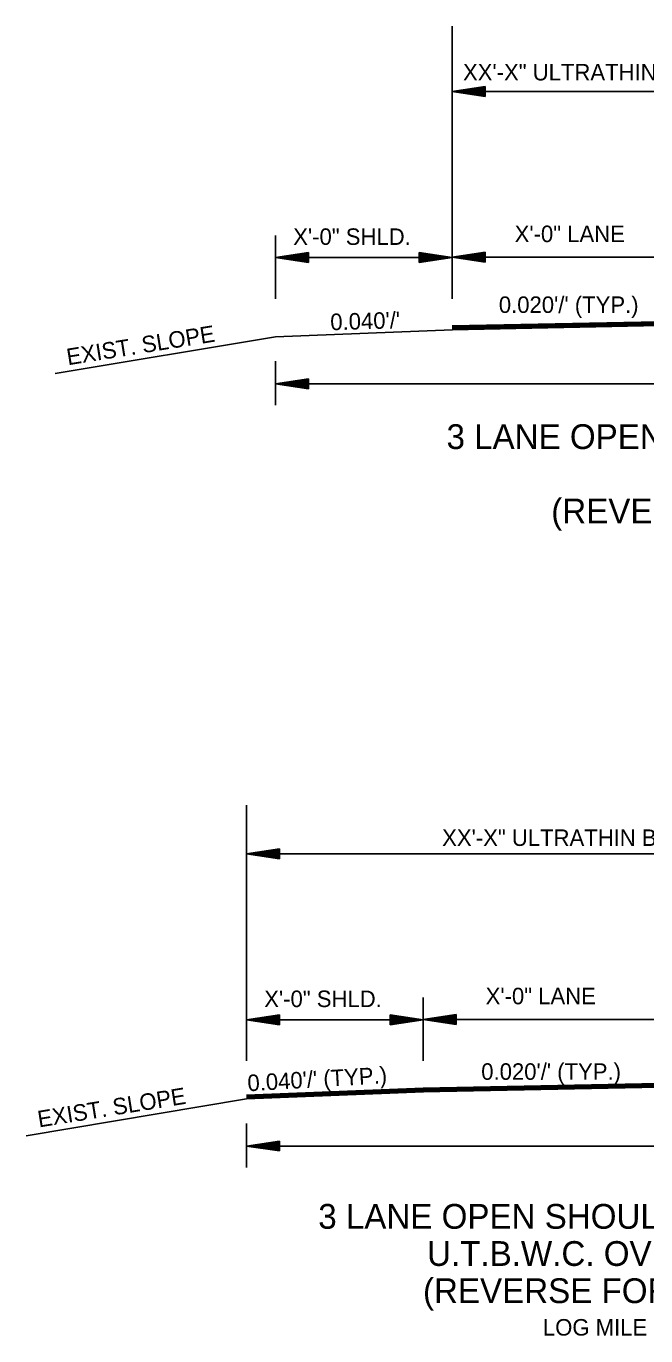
# Model space of a CAD drawing. Extents: x 544199 to 1930787, y -1968972 to 596640.
# Drawn here: x 551580 to 551862, y -1953290 to -1952695 of the extents above; entities that cross this region are included whole.
import ezdxf

# ---------------------------------------------------------------- set-up
doc = ezdxf.new("R2010")
doc.units = 0
doc.layers.add('R_Draft', color=7, linetype='Continuous')

msp = doc.modelspace()

# ---------------------------------------------------------------- linework, layer by layer
at = {"layer": 'R_Draft'}
for p, q in [((551773.61, -1952818.73), (551773.61, -1952695)), ((551788.61, -1952722.45), (551773.61, -1952724.7)), ((551773.61, -1952724.7), (552133.8, -1952724.7)), ((551788.61, -1952726.95), (551773.61, -1952724.7)), ((551788.61, -1952722.83), (551776.12, -1952724.7)), ((551788.61, -1952726.58), (551776.12, -1952724.7)), ((551788.61, -1952723.21), (551778.7, -1952724.7)), ((551788.61, -1952726.19), (551778.7, -1952724.7)), ((551788.61, -1952723.58), (551781.19, -1952724.7)), ((551788.61, -1952725.82), (551781.19, -1952724.7)), ((551788.61, -1952723.97), (551783.74, -1952724.7)), ((551788.61, -1952725.43), (551783.74, -1952724.7)), ((551788.61, -1952724.35), (551786.24, -1952724.7)), ((551788.61, -1952725.05), (551786.24, -1952724.7)), ((551788.61, -1952726.95), (551788.61, -1952722.45)), ((551693.35, -1952790), (551693.35, -1952818.73)), ((551773.61, -1952818.56), (551773.61, -1952790.01)), ((551708.35, -1952797.82), (551693.35, -1952800.07)), ((551773.61, -1952800.07), (551693.35, -1952800.07)), ((551708.35, -1952802.32), (551693.35, -1952800.07)), ((551708.35, -1952798.2), (551695.86, -1952800.07)), ((551708.35, -1952801.95), (551695.86, -1952800.07)), ((551708.35, -1952798.58), (551698.44, -1952800.07)), ((551708.35, -1952801.56), (551698.44, -1952800.07)), ((551708.35, -1952798.95), (551700.93, -1952800.07)), ((551708.35, -1952801.19), (551700.93, -1952800.07)), ((551708.35, -1952799.34), (551703.48, -1952800.07)), ((551708.35, -1952800.8), (551703.48, -1952800.07)), ((551708.35, -1952799.72), (551705.98, -1952800.07)), ((551708.35, -1952800.42), (551705.98, -1952800.07)), ((551708.35, -1952802.32), (551708.35, -1952797.82)), ((551758.61, -1952797.82), (551773.61, -1952800.07)), ((551758.61, -1952797.82), (551758.61, -1952802.32)), ((551758.61, -1952798.2), (551771.11, -1952800.07)), ((551758.61, -1952798.58), (551768.53, -1952800.07)), ((551758.61, -1952798.95), (551766.03, -1952800.07)), ((551758.61, -1952799.34), (551763.49, -1952800.07)), ((551758.61, -1952799.72), (551760.98, -1952800.07)), ((551758.61, -1952802.32), (551773.61, -1952800.07)), ((551758.61, -1952800.81), (551763.49, -1952800.07)), ((551758.61, -1952801.56), (551768.53, -1952800.07)), ((551758.61, -1952801.95), (551771.11, -1952800.07)), ((551758.61, -1952801.19), (551766.03, -1952800.07)), ((551758.61, -1952800.42), (551760.98, -1952800.07)), ((551788.61, -1952797.65), (551773.61, -1952799.9)), ((551893.61, -1952799.9), (551773.61, -1952799.9)), ((551788.61, -1952802.15), (551773.61, -1952799.9)), ((551788.61, -1952798.03), (551776.12, -1952799.9)), ((551788.61, -1952801.78), (551776.12, -1952799.9)), ((551788.61, -1952798.41), (551778.7, -1952799.9)), ((551788.61, -1952801.39), (551778.7, -1952799.9)), ((551788.61, -1952798.78), (551781.19, -1952799.9)), ((551788.61, -1952801.02), (551781.19, -1952799.9)), ((551788.61, -1952799.17), (551783.74, -1952799.9)), ((551788.61, -1952800.63), (551783.74, -1952799.9)), ((551788.61, -1952799.55), (551786.24, -1952799.9)), ((551788.61, -1952800.25), (551786.24, -1952799.9)), ((551788.61, -1952802.15), (551788.61, -1952797.65)), ((552013.54, -1952826.31), (551773.61, -1952831.11)), ((552013.54, -1952826.61), (551773.62, -1952831.41)), ((552013.54, -1952826.91), (551773.62, -1952831.71)), ((552013.54, -1952827.21), (551773.63, -1952832.01)), ((552013.54, -1952827.51), (551773.64, -1952832.31)), ((552013.54, -1952827.81), (551773.64, -1952832.61)), ((552013.54, -1952828.01), (551773.65, -1952832.81)), ((551693.35, -1952836.02), (551593.28, -1952852.69)), ((551693.35, -1952836.02), (551773.68, -1952832.8)), ((551693.35, -1952847.12), (551693.35, -1952867.12)), ((551708.35, -1952855.12), (551693.35, -1952857.37)), ((551708.35, -1952855.49), (551695.86, -1952857.37)), ((551708.35, -1952859.62), (551708.35, -1952855.12)), ((551693.35, -1952857.37), (552213.8, -1952857.37)), ((551708.35, -1952859.62), (551693.35, -1952857.37)), ((551708.35, -1952859.24), (551695.86, -1952857.37)), ((551708.35, -1952855.87), (551698.44, -1952857.37)), ((551708.35, -1952858.86), (551698.44, -1952857.37)), ((551708.35, -1952856.25), (551700.93, -1952857.37)), ((551708.35, -1952858.48), (551700.93, -1952857.37)), ((551708.35, -1952856.63), (551703.48, -1952857.37)), ((551708.35, -1952858.09), (551703.48, -1952857.37)), ((551708.35, -1952857.01), (551705.98, -1952857.37)), ((551708.35, -1952857.72), (551705.98, -1952857.37)), ((551680.18, -1953048.62), (551680.18, -1953164.77)), ((551695.18, -1953068.49), (551680.18, -1953070.74)), ((551695.18, -1953068.87), (551682.69, -1953070.74)), ((551695.18, -1953069.25), (551685.27, -1953070.74)), ((551695.18, -1953069.62), (551687.76, -1953070.74)), ((551695.18, -1953072.99), (551695.18, -1953068.49)), ((551680.18, -1953070.74), (552200.63, -1953070.74)), ((551695.18, -1953072.99), (551680.18, -1953070.74)), ((551695.18, -1953072.62), (551682.69, -1953070.74)), ((551695.18, -1953072.23), (551685.27, -1953070.74)), ((551695.18, -1953071.86), (551687.76, -1953070.74)), ((551695.18, -1953070.01), (551690.31, -1953070.74)), ((551695.18, -1953071.47), (551690.31, -1953070.74)), ((551695.18, -1953070.39), (551692.81, -1953070.74)), ((551695.18, -1953071.09), (551692.81, -1953070.74)), ((551760.44, -1953164.77), (551760.44, -1953136.04)), ((551760.44, -1953164.6), (551760.44, -1953136.05)), ((551695.18, -1953143.86), (551680.18, -1953146.11)), ((551760.44, -1953146.11), (551680.18, -1953146.11)), ((551695.18, -1953148.36), (551680.18, -1953146.11)), ((551695.18, -1953144.24), (551682.69, -1953146.11)), ((551695.18, -1953147.99), (551682.69, -1953146.11)), ((551695.18, -1953144.62), (551685.27, -1953146.11)), ((551695.18, -1953147.6), (551685.27, -1953146.11)), ((551695.18, -1953144.99), (551687.76, -1953146.11)), ((551695.18, -1953147.23), (551687.76, -1953146.11)), ((551695.18, -1953145.38), (551690.31, -1953146.11)), ((551695.18, -1953146.84), (551690.31, -1953146.11)), ((551695.18, -1953145.76), (551692.81, -1953146.11)), ((551695.18, -1953146.46), (551692.81, -1953146.11)), ((551695.18, -1953148.36), (551695.18, -1953143.86)), ((551745.44, -1953143.86), (551760.44, -1953146.11)), ((551745.44, -1953143.86), (551745.44, -1953148.36)), ((551745.44, -1953144.24), (551757.94, -1953146.11)), ((551745.44, -1953144.62), (551755.36, -1953146.11)), ((551745.44, -1953144.99), (551752.86, -1953146.11)), ((551745.44, -1953145.38), (551750.32, -1953146.11)), ((551745.44, -1953145.76), (551747.81, -1953146.11)), ((551745.44, -1953148.36), (551760.44, -1953146.11)), ((551745.44, -1953146.85), (551750.32, -1953146.11)), ((551745.44, -1953147.6), (551755.36, -1953146.11)), ((551745.44, -1953147.99), (551757.94, -1953146.11)), ((551745.44, -1953147.23), (551752.86, -1953146.11)), ((551745.44, -1953146.46), (551747.81, -1953146.11)), ((551775.44, -1953143.69), (551760.44, -1953145.94)), ((551880.44, -1953145.94), (551760.44, -1953145.94)), ((551775.44, -1953148.19), (551760.44, -1953145.94)), ((551775.44, -1953144.07), (551762.95, -1953145.94)), ((551775.44, -1953147.82), (551762.95, -1953145.94)), ((551775.44, -1953144.45), (551765.53, -1953145.94)), ((551775.44, -1953147.43), (551765.53, -1953145.94)), ((551775.44, -1953144.82), (551768.03, -1953145.94)), ((551775.44, -1953147.06), (551768.03, -1953145.94)), ((551775.44, -1953145.21), (551770.57, -1953145.94)), ((551775.44, -1953146.67), (551770.57, -1953145.94)), ((551775.44, -1953145.59), (551773.07, -1953145.94)), ((551775.44, -1953146.29), (551773.07, -1953145.94)), ((551775.44, -1953148.19), (551775.44, -1953143.69)), ((552000.37, -1953172.35), (551760.44, -1953177.15)), ((552000.37, -1953172.65), (551760.45, -1953177.45)), ((552000.37, -1953172.95), (551760.46, -1953177.75)), ((552000.37, -1953173.25), (551760.46, -1953178.05)), ((552000.37, -1953173.55), (551760.47, -1953178.35)), ((552000.37, -1953173.85), (551760.47, -1953178.65)), ((552000.37, -1953174.05), (551760.48, -1953178.85)), ((551680.18, -1953182.06), (551580.11, -1953198.74)), ((551680.11, -1953180.36), (551760.44, -1953177.15)), ((551680.13, -1953180.66), (551760.46, -1953177.45)), ((551680.14, -1953180.96), (551760.47, -1953177.75)), ((551680.15, -1953181.26), (551760.48, -1953178.05)), ((551680.16, -1953181.56), (551760.49, -1953178.35)), ((551680.17, -1953181.86), (551760.5, -1953178.65)), ((551680.18, -1953182.06), (551760.51, -1953178.85)), ((551680.18, -1953193.16), (551680.18, -1953213.16)), ((551695.18, -1953201.16), (551680.18, -1953203.41)), ((551680.18, -1953203.41), (552200.63, -1953203.41)), ((551695.18, -1953205.66), (551680.18, -1953203.41)), ((551695.18, -1953201.53), (551682.69, -1953203.41)), ((551695.18, -1953205.28), (551682.69, -1953203.41)), ((551695.18, -1953201.91), (551685.27, -1953203.41)), ((551695.18, -1953204.9), (551685.27, -1953203.41)), ((551695.18, -1953202.29), (551687.76, -1953203.41)), ((551695.18, -1953204.52), (551687.76, -1953203.41)), ((551695.18, -1953202.67), (551690.31, -1953203.41)), ((551695.18, -1953204.13), (551690.31, -1953203.41)), ((551695.18, -1953203.05), (551692.81, -1953203.41)), ((551695.18, -1953203.76), (551692.81, -1953203.41)), ((551695.18, -1953205.66), (551695.18, -1953201.16))]:
    msp.add_line(p, q, dxfattribs=at)

# ---------------------------------------------------------------- texts
for s, height, p in [('XX\'-X" ULTRATHIN BONDED WEARING COURSE (5/8" - TYPE B)', 7.5, (551778.5, -1952719.63)), ('X\'-0" SHLD.', 7.5, (551701.39, -1952794.3)), ('X\'-0" LANE', 7.5, (551801.96, -1952793.04)), ("0.020'/' (TYP.)", 7.5, (551794.78, -1952825.19)), ('3 LANE OPEN SHOULDER (WESTBOUND PASSING LANE)', 11.25, (551771.02, -1952886.97)), ('(REVERSE FOR EASTBOUND PASSING LANE)', 11.25, (551818.59, -1952920.72)), ('XX\'-X" ULTRATHIN BONDED WEARING COURSE (5/8" - TYPE B)', 7.5, (551769.03, -1953067.18)), ('X\'-0" SHLD.', 7.5, (551688.22, -1953140.34)), ('X\'-0" LANE', 7.5, (551788.79, -1953139.08)), ("0.020'/' (TYP.)", 7.5, (551786.79, -1953173.36)), ('3 LANE OPEN SHOULDER (WESTBOUND PASSING LANE) ', 11.25, (551712.77, -1953240.98)), ('U.T.B.W.C. OVERLAY INCLUDING SHOULDERS', 11.25, (551762.2, -1953257.85)), ('(REVERSE FOR EASTBOUND PASSING LANE)', 11.25, (551760.34, -1953274.73)), ('LOG MILE X.XX TO LOG MILE X.XX', 7.5, (551814.8, -1953289.48))]:
    msp.add_text(s, height=height, dxfattribs=at).set_placement(p)
for s, rotation, p in [("0.040'/'", 1.70227, (551718.34, -1952833.06)), ('EXIST. SLOPE', 9.15344, (551599.1, -1952848.96)), ("0.040'/' (TYP.)", 3.3852, (551680.83, -1953178.6)), ('EXIST. SLOPE', 9.15344, (551585.93, -1953195))]:
    msp.add_text(s, height=7.5, rotation=rotation, dxfattribs=at).set_placement(p)

doc.saveas('drawing.dxf')
